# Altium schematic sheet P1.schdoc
size 297 x 209 mm; Symbol: Drawing-Symbol_A4; @Project Name: claude_buddy_v0.3; @Page Count: 1; @Update Date: 2026-10-19; @Create Date: 2026-10-19; @Schematic Name: Schematic1; @Page No: 1; @Page Name: P1; Company: EasyEDA.com; Version: V1.0; Page Size: A4; Device: Drawing-Symbol_A4; @Create Time: 07:10:46; @Update Time: 07:10:46; Border: 1; Width: 1170; Height: 825; Region Start: 1; X Region Count: 6; Y Region Count: 4; Blade Width: 10; Title Block Position: 3; @Board Name: Board1
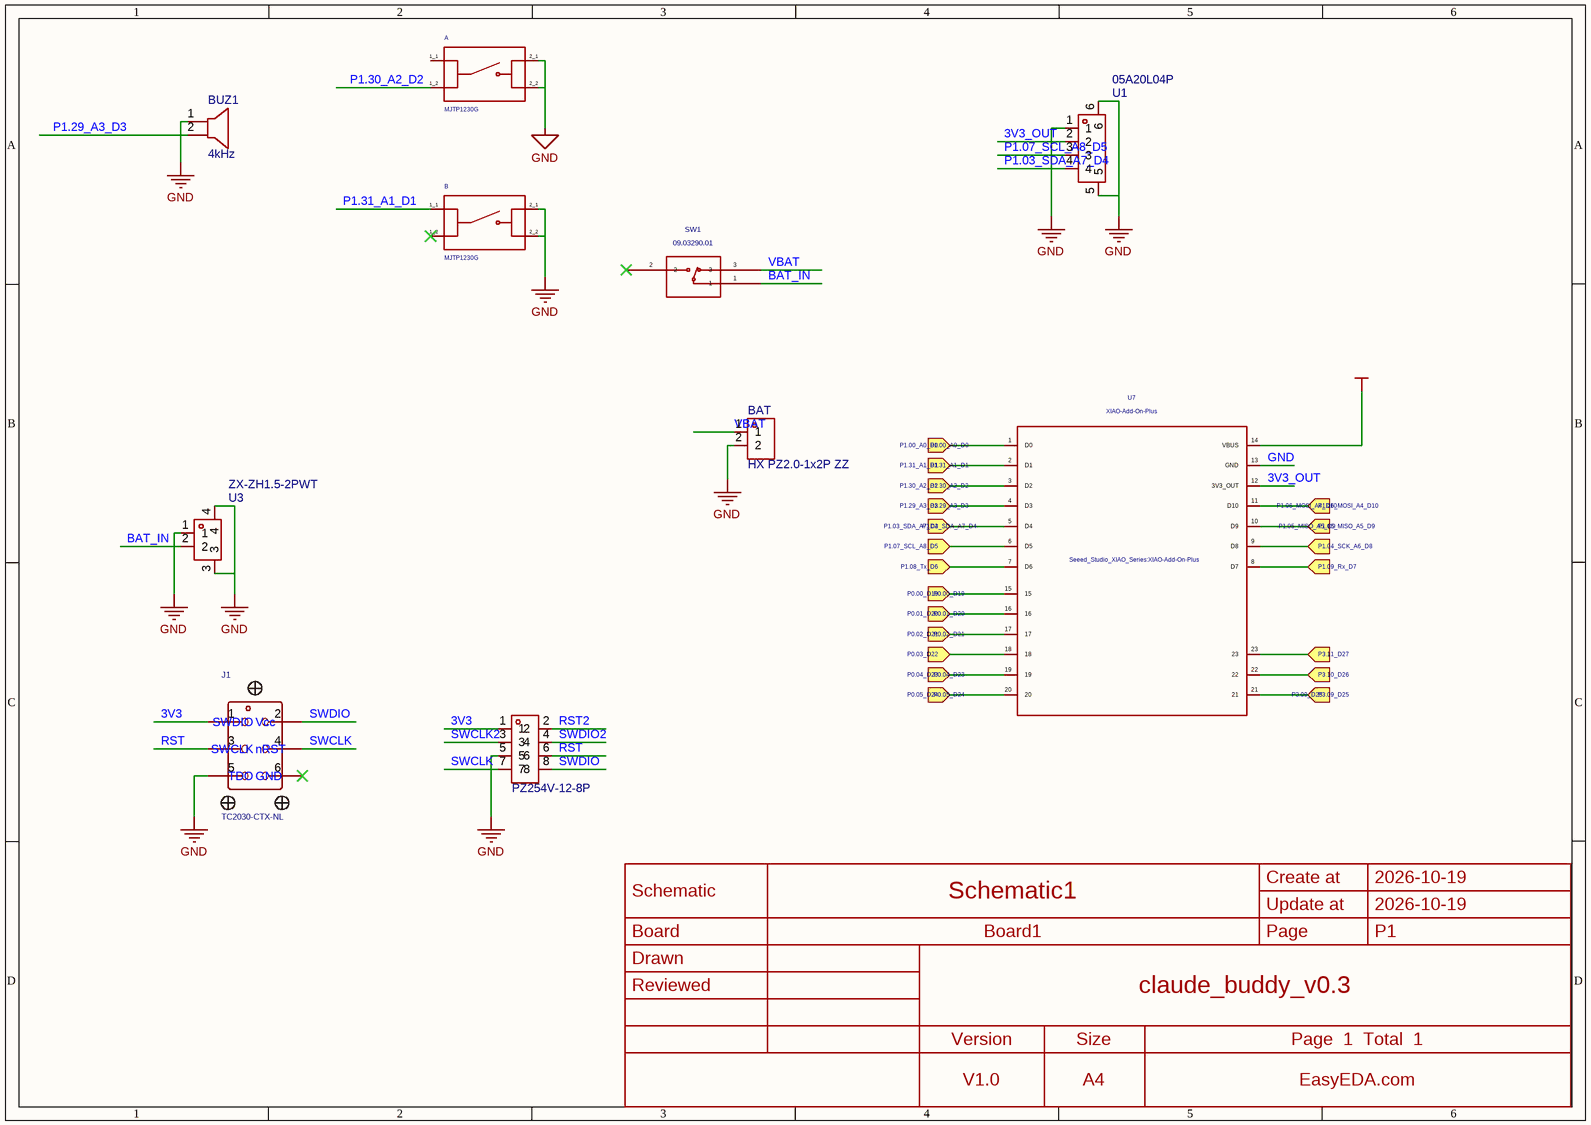
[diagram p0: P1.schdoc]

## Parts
A  value MJTP1230G  [SW_MJTP1230G]
B  value MJTP1230G  [SW_MJTP1230G]
BAT  HX PZ2.0-1x2P ZZ  [CB_HDR-TH_2P-P2.00-V-M]
BUZ1  4kHz  [BUZ-SMD_L9.0-W9.0_PKMCS0909E4000-R1]
J1  TC2030-CTX-NL  [TC2030-CTX-NL]
SW1  value 09.03290.01  [09.03290_EAO]
SWD  PZ254V-12-8P  [CB_HDR-TH_8P-P2.54-V-M-R2-C4-S2.54]
U1  05A20L04P  [FPC-SMD_4P-P0.50_05A20L4P]
U3  ZX-ZH1.5-2PWT  [CONN-SMD_2P-P1.50_ZX-ZH1.5-2PWT]
U7  value XIAO-Add-On-Plus  Origin Footprint: Seeed_Studio_XIAO_Series:XIAO-Add-On-Plus  [Claude_buddy_Seeed_Studio_XIAO_Series:XIAO-Add-On-PRO]  (hidden comment: Seeed_Studio_XIAO_Series_XIAO-Add-On-Plus)

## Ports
P0.00_D19 (in), P0.01_D20 (in), P0.02_D21 (in), P0.03_D22 (in), P0.04_D23 (in), P0.05_D24 (in), P1.00_A0_D0 (in), P1.03_SDA_A7_D4 (in), P1.04_SCK_A6_D8 (in), P1.05_MISO_A5_D9 (in), P1.06_MOSI_A4_D10 (in), P1.07_SCL_A8_D5 (in), P1.08_Tx_D6 (in), P1.09_Rx_D7 (in), P1.29_A3_D3 (in), P1.30_A2_D2 (in), P1.31_A1_D1 (in), P3.09_D25 (in), P3.10_D26 (in), P3.11_D27 (in)

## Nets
GND: A.2_1 A.2_2 B.2_1 B.2_2 BAT.2 BUZ1.1 J1.5(GND) SWD.5 U1.1 U1.5 U1.6 U3.1 U3.3 U3.4 U7.13(GND)
power_+5V: U7.14(VBUS)
3V3: J1.1(Vcc) SWD.1
3V3_OUT: U1.2 U7.12(3V3_OUT)
BAT_IN: SW1.1 U3.2
P0.00_D19: U7.15 ; port P0.00_D19
P0.01_D20: U7.16 ; port P0.01_D20
P0.02_D21: U7.17 ; port P0.02_D21
P0.03_D22: U7.18 ; port P0.03_D22
P0.04_D23: U7.19 ; port P0.04_D23
P0.05_D24: U7.20 ; port P0.05_D24
P1.00_A0_D0: U7.1(D0) ; port P1.00_A0_D0
P1.03_SDA_A7_D4: U1.4 U7.5(D4) ; port P1.03_SDA_A7_D4
P1.04_SCK_A6_D8: U7.9(D8) ; port P1.04_SCK_A6_D8
P1.05_MISO_A5_D9: U7.10(D9) ; port P1.05_MISO_A5_D9
P1.06_MOSI_A4_D10: U7.11(D10) ; port P1.06_MOSI_A4_D10
P1.07_SCL_A8_D5: U1.3
P1.07_SCL_A8_D5: U7.6(D5) ; port P1.07_SCL_A8_D5  [a separate net that carries the same name]
P1.08_Tx_D6: U7.7(D6) ; port P1.08_Tx_D6
P1.09_Rx_D7: U7.8(D7) ; port P1.09_Rx_D7
P1.29_A3_D3: BUZ1.2 U7.4(D3) ; port P1.29_A3_D3
P1.30_A2_D2: A.1_2 U7.3(D2) ; port P1.30_A2_D2
P1.31_A1_D1: B.1_1 U7.2(D1) ; port P1.31_A1_D1
P3.09_D25: U7.21 ; port P3.09_D25
P3.10_D26: U7.22 ; port P3.10_D26
P3.11_D27: U7.23 ; port P3.11_D27
RST: J1.3(nRST) SWD.6
RST2: SWD.2
SWCLK: J1.4(SWCLK) SWD.7
SWCLK2: SWD.3
SWDIO: J1.2(SWDIO) SWD.8
SWDIO2: SWD.4
VBAT: BAT.1 SW1.3

Not connected (* = marked no-connect by the designer): A 1_1; B 1_2*; J1 6(TDO)*; SW1 2*

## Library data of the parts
A B = MJTP1230G: MANUFACTURER: APEM; AddInBom: yes
BAT = HX PZ2.0-1x2P ZZ: Pin Structure:1x2P Pitch:2mm Row Spacing:- Circluar Pins/Square Pins:Pin Header Mounting Type:Through Hole Number of Rows:1 Number of Pins:2P Current Rating:1.5A Voltage Rating (Max):500V Length of Mating Pin:3.9mm Insulation Height:2mm Length of End Conn; Manufacturer: hanxia(韩下); AddInBom: yes; ModelId: e17c75cfcc494cbc851ad48b77341f630819f05c4eef4c71ace90d822a990e87; ModelName: HDR-TH_2P-P2.00-M-LI-1X2P; ModelTransform: 157.48,78.74,0,0,0,0,0,0,-118.11; Pin Structure: 1x2P; Pitch: 2mm; Current Rating: 1.5A; Voltage Rating (Max): 500V
BUZ1 = PKMCS0909E4000-R1: Driver Circuitry:Passive (Externally Driven) Technology:Piezoelectric Voltage Rating:- Voltage - Supply:12.5V Voltage - Supply:12.5V Frequency:4kHz Current Consumption:- Sound Pressure Level(SPL):65dB Diameter(φD):- Length:9mm Width:9mm Height:1.9mm Opera; Manufacturer: muRata(村田); 3D Model: 55e0b563f1aa4d65a99e18d0438535180819f05c4eef4c71ace90d822a990e87; 3D Model Transform: 354.40874,354.33,0,0,0,0,0,0,0; Voltage - Supply: 12.5V; Sound Pressure Level(SPL): 65dB; AddInBom: yes
J1 = TC2030-CTX-NL: Manufacturer: TagConnect; AddInBom: yes
SW1 = 09.03290.01: AddInBom: yes
SWD = PZ254V-12-8P: Pin Structure:2x4P Pitch:2.54mm Row Spacing:2.54mm Circluar Pins/Square Pins:Pin Header Mounting Type:Through Hole Number of Rows:2 Number of Pins:8P Current Rating:- Voltage Rating (Max):- Length of Mating Pin:6mm Insulation Height:2.5mm Length of End Co; Manufacturer: XFCN(兴飞); AddInBom: yes; ModelId: 47b5ce995b664298ab05f1b74b77106f43db7fa9743548f69de3f826aa2e2726; ModelName: HDR-TH_8P-P2.54-M-LI-2X4P; ModelTransform: 399.999,200,0,0,0,0,0,0,-118.11; Pin Structure: 2x4P; Pitch: 2.54mm
U1 = 05A20L04P: Locking Feature:Hinged Lid Contact Type:Bottom Contact Number of Contacts:4P Pitch:0.5mm Mounting Type:Surface Mount, Right Angle FFC, FCB Thickness:0.3mm FFC, FCB Thickness:0.3mm Height Above Board:2mm Contact Material:Phosphor Bronze Contact Plating:Tin; Manufacturer: HanElectricity(瀚源); Number of Contacts: 4P; Pitch: 0.5mm; FFC, FCB Thickness: 0.3mm; Rated Voltage (Max): 50V; Current Rating (Max): 400mA; AddInBom: yes
U3 = ZX-ZH1.5-2PWT: Pins Structure:1x2P Pitch:1.5mm Mounting Type:Surface Mount, Right Angle Reference Series:ZH Number of Pins:2P Number of Rows:1 Number of PINs Per Row:2 Row Spacing:- Current Rating:1A Contact Material:Brass Contact Plating:Tin Operating Temperature:-25℃~; Manufacturer: Megastar(兆星); 3D Model: d21e540b9b044195a4ed837c64072d89a591df26b586487b9b65f5f7abb1ee18; 3D Model Transform: 236.614,255.905,0,0,0,0,-0.003,-28.858,0; Pins Structure: 1x2P; Pitch: 1.5mm; Reference Series: ZH; Number of PINs Per Row: 2; Current Rating: 1A; Voltage Rating: 250V; Plastic Material: LCP; Supplementary Features: Auxiliary Solder Pin; Z-Height of the Board: 3.8mm; X-Length of Bottom Edge on Board (Spacing Line): 6mm; AddInBom: yes
U7 = Seeed_Studio_XIAO_Series_XIAO-Add-On-Plus: AddInBom: yes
